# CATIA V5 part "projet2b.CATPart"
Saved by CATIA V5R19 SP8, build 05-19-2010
Part number: projet2b
Bounding box of the stored display mesh (mm): x 0 to 141.225, y -150 to 150, z -75 to 75
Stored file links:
  C:\Documents and Settings\msamadi\Bureau\projet 2 vendredi\projet2b.CATPart
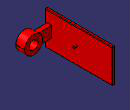
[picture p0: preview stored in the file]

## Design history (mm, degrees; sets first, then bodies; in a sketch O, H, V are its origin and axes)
Parameters
  Longueur = 10 mm
Body1 (main body)
  Sketch1 on yz-plane, origin (0, 0, 0), H (0, 1, 0), V (0, 0, 1)
    line L1 (-150, 75) -> (150, 75)
    line L2 (150, 75) -> (150, -75)
    line L3 (150, -75) -> (-150, -75)
    line L4 (-150, -75) -> (-150, 75)
    length L1 = 300 {= Longueur *30}
    length L2 = 150 {= Longueur *15}
    distance V L2 = 150 {= Longueur *15}
    distance H L1 = 75 {= Longueur *7.5}
    horizontal: L1 H, L3 H
    vertical: L2 V, L4 V
  Pad1: profile Sketch1, direction (1, 0, 0), length 10 {= Longueur *1}
  Sketch2 on end face of Pad1, origin (10, 0, 0), H (0, 1, 0), V (0, 0, 1)
    line L1 (-140, 25) -> (-120, 25)
    line L2 (-120, 25) -> (-120, -25)
    line L3 (-120, -25) -> (-140, -25)
    line L4 (-140, -25) -> (-140, 25)
    length L2 = 50 {= Longueur *5}
    length L1 = 20 {= Longueur *2}
    distance L1 H = 25 {= Longueur *2.5}
    distance L2 V = 120 {= Longueur *12}
    horizontal: L1 H, L3 H
    vertical: L2 V, L4 V
  Pad2: profile Sketch2, direction (1, 0, 0), length 60 {= Longueur *6}
  Sketch3 on face of Pad2 from Sketch2.L4, origin (0, -140, 0), H (1, 0, 0), V (0, 0, 1)
    arc A1 centre (101.225, 0) radius 40 from (70, 25) to (70, -25) ccw
    point P2 (70, 25)
    point P3 (70, -25)
    reference projected point E1 (70, 25) from vertex [face of Pad2 from Sketch2.L1 | end face of Pad2 | face of Pad2 from Sketch2.L4]
    reference projected point E2 (70, -25) from vertex [face of Pad2 from Sketch2.L3 | end face of Pad2 | face of Pad2 from Sketch2.L4]
    radius A1 = 40 {= Longueur *4}
    coincidence: P2 E1, E2 P3
  Pocket1: profile Sketch3, direction (0, 1, 0), through (limit type 6), offset 0 {= Longueur *0}
  Sketch4 on face of Pad1 from Sketch1.L4, origin (0, -150, 0), H (1, 0, 0), V (0, 0, 1)
    circle A1 centre (101.225, 0) radius 40
    point P1 (101.225, 0)
    reference projected arc E1 centre (101.225, 0) radius 40 from (70, 25) to (70, -25) ccw from edge [face of Pad2 from Sketch2.L4 | face of Pocket1 from Sketch3.A1]
    distance P1 A1 = 40 {= Longueur *4}
    coincidence: P1 H
    concentricity: A1 E1
  Pad3: profile Sketch4, direction (0, 1, 0), length 40 {= Longueur *4}
  Sketch5 on end face of Pad1, origin (10, 0, 0), H (0, 1, 0), V (0, 0, 1)
    circle A1 centre (-10, 0) radius 5
    point P1 (-10, 0)
    distance P1 V = 10 {= Longueur *1}
    distance P1 A1 = 5 {= Longueur *0.5}
    coincidence: P1 H
  Pad4: profile Sketch5, direction (1, 0, 0), length 11 {= Longueur *1.1}
  Sketch6 on start face of Pad3, origin (0, -150, 0), H (1, 0, 0), V (0, 0, 1)
    circle A1 centre (101.225, 0) radius 20
    point P1 (101.225, 0)
    reference projected circle E1 centre (101.225, 0) radius 40 from edge [face of Pad3 from Sketch4.A1 | start face of Pad3]
    distance P1 A1 = 20 {= Longueur *2}
    coincidence: P1 H
    concentricity: A1 E1
  Pocket2: profile Sketch6, direction (0, 1, 0), through (limit type 6), offset 0 {= Longueur *0}
  Fillet1: radius 2.5 {= Longueur *0.25}, on edge [face of Pad1 from Sketch1.L2 | end face of Pad1]; edge [face of Pad1 from Sketch1.L3 | end face of Pad1]; edge [face of Pad1 from Sketch1.L1 | end face of Pad1]; edge [face of Pad1 from Sketch1.L4 | end face of Pad1]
